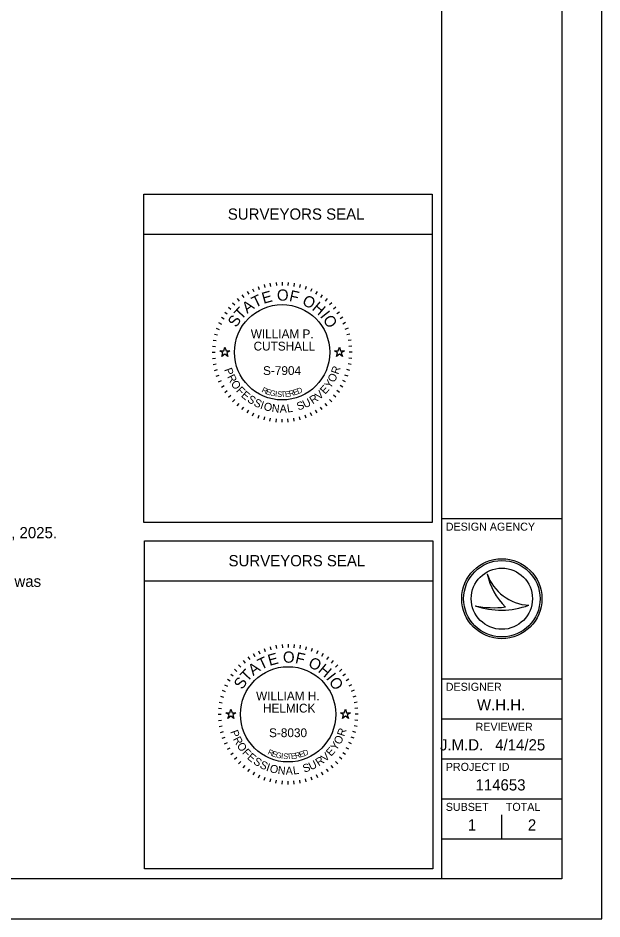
# Model space of a CAD drawing. Extents: x 0 to 34, y 0 to 22.
# Drawn here: x 26.71 to 34, y 0 to 11.25 of the extents above; entities that cross this region are included whole.
import ezdxf

# ---------------------------------------------------------------- set-up
doc = ezdxf.new("R2010")
doc.units = 0
for name, color, linetype in [('SH_Border', 7, 'Continuous'), ('SH_Cut_Line', 7, 'Continuous'), ('SH_Data', 7, 'Continuous'), ('SH_Seal', 7, 'Continuous'), ('SH_Text', 7, 'Continuous')]:
    doc.layers.add(name, color=color, linetype=linetype)

msp = doc.modelspace()

# ---------------------------------------------------------------- linework, layer by layer
at = {"layer": 'SH_Border'}
for p, q in [((32, 0.5), (32, 21.5)), ((32, 5), (33.5, 5)), ((32, 3), (33.5, 3)), ((32, 2.5), (33.5, 2.5)), ((32, 2), (33.5, 2)), ((32, 1.5), (33.5, 1.5)), ((32, 1), (33.5, 1))]:
    msp.add_line(p, q, dxfattribs=at)
msp.add_lwpolyline([(1.5, 21.5), (33.5, 21.5), (33.5, 0.5), (1.5, 0.5)], close=True, dxfattribs=at)
at = {"layer": 'SH_Cut_Line'}
msp.add_lwpolyline([(0, 0), (34, 0), (34, 22), (0, 22)], close=True, dxfattribs=at)
at = {"layer": 'SH_Data'}
for p, q in [((28.279, 8.554), (31.879, 8.554)), ((32.567, 4.31), (32.567, 4.31)), ((28.288, 4.225), (31.888, 4.225)), ((32.75, 4), (32.75, 4)), ((32.417, 3.91), (32.417, 3.91)), ((33.087, 3.919), (33.087, 3.919)), ((32.75, 1), (32.75, 1.3))]:
    msp.add_line(p, q, dxfattribs=at)
for points in [[(28.279, 9.054), (31.879, 9.054), (31.879, 4.954), (28.279, 4.954)], [(28.288, 4.725), (31.888, 4.725), (31.888, 0.625), (28.288, 0.625)]]:
    msp.add_lwpolyline(points, close=True, dxfattribs=at)
for radius in [0.5, 0.477, 0.477, 0.382]:
    msp.add_circle((32.75, 4), radius, dxfattribs=at)
for centre, radius, start, end in [((33.116, 4.498), 0.58, 198.9257, 198.9319), ((33.347, 4.47), 0.796, 191.6379, 191.6421), ((33.116, 4.498), 0.58, 198.9319, 267.1657), ((33.347, 4.47), 0.796, 191.6421, 226.0947), ((32.739, 4.87), 1.013, 251.4576, 290.0832), ((32.648, 5.154), 1.266, 259.4964, 259.4995), ((32.739, 4.87), 1.013, 251.4527, 251.4576), ((32.648, 5.154), 1.266, 259.4995, 276.6672)]:
    msp.add_arc(centre, radius, start, end, dxfattribs=at)
at = {"layer": 'SH_Seal'}
for p, q in [((29.708, 7.901), (29.722, 7.863)), ((29.781, 7.924), (29.791, 7.885)), ((29.855, 7.94), (29.862, 7.901)), ((29.931, 7.95), (29.935, 7.91)), ((30.007, 7.953), (30.007, 7.913)), ((30.084, 7.95), (30.08, 7.91)), ((30.159, 7.94), (30.152, 7.901)), ((30.234, 7.924), (30.224, 7.885)), ((30.307, 7.901), (30.293, 7.863)), ((29.506, 7.795), (29.528, 7.762)), ((29.57, 7.836), (29.59, 7.802)), ((29.638, 7.871), (29.655, 7.835)), ((30.377, 7.871), (30.36, 7.835)), ((30.445, 7.836), (30.425, 7.802)), ((30.509, 7.795), (30.486, 7.762)), ((29.389, 7.697), (29.417, 7.669)), ((29.445, 7.749), (29.471, 7.718)), ((30.57, 7.749), (30.544, 7.718)), ((30.626, 7.697), (30.598, 7.669)), ((29.291, 7.58), (29.323, 7.557)), ((29.337, 7.641), (29.368, 7.615)), ((30.678, 7.641), (30.647, 7.615)), ((30.724, 7.58), (30.691, 7.557)), ((29.214, 7.448), (29.251, 7.431)), ((29.25, 7.516), (29.284, 7.496)), ((30.765, 7.516), (30.731, 7.496)), ((30.8, 7.448), (30.764, 7.431)), ((29.185, 7.378), (29.223, 7.364)), ((30.83, 7.378), (30.792, 7.364)), ((29.146, 7.23), (29.185, 7.223)), ((29.162, 7.305), (29.201, 7.295)), ((30.853, 7.305), (30.814, 7.295)), ((30.869, 7.23), (30.83, 7.223)), ((29.136, 7.155), (29.176, 7.151)), ((30.879, 7.155), (30.839, 7.151)), ((29.132, 7.078), (29.172, 7.078)), ((29.136, 7.002), (29.176, 7.006)), ((30.879, 7.002), (30.839, 7.006)), ((30.882, 7.078), (30.842, 7.078)), ((29.146, 6.927), (29.185, 6.933)), ((30.869, 6.927), (30.83, 6.933)), ((29.162, 6.852), (29.201, 6.862)), ((29.185, 6.779), (29.223, 6.793)), ((30.83, 6.779), (30.792, 6.793)), ((30.853, 6.852), (30.814, 6.862)), ((29.214, 6.709), (29.251, 6.726)), ((29.25, 6.641), (29.284, 6.661)), ((30.765, 6.641), (30.731, 6.661)), ((30.8, 6.709), (30.764, 6.726)), ((29.291, 6.577), (29.323, 6.6)), ((29.337, 6.516), (29.368, 6.542)), ((30.678, 6.516), (30.647, 6.542)), ((30.724, 6.577), (30.691, 6.6)), ((29.389, 6.46), (29.417, 6.488)), ((29.445, 6.408), (29.471, 6.439)), ((30.57, 6.408), (30.544, 6.439)), ((30.626, 6.46), (30.598, 6.488)), ((29.506, 6.362), (29.528, 6.394)), ((29.57, 6.321), (29.59, 6.355)), ((29.638, 6.285), (29.655, 6.322)), ((30.377, 6.285), (30.36, 6.322)), ((30.445, 6.321), (30.425, 6.355)), ((30.509, 6.362), (30.486, 6.394)), ((29.708, 6.256), (29.722, 6.294)), ((29.781, 6.233), (29.791, 6.272)), ((29.855, 6.217), (29.862, 6.256)), ((29.931, 6.207), (29.935, 6.247)), ((30.007, 6.203), (30.007, 6.243)), ((30.084, 6.207), (30.08, 6.247)), ((30.159, 6.217), (30.152, 6.256)), ((30.234, 6.233), (30.224, 6.272)), ((30.307, 6.256), (30.293, 6.294)), ((29.783, 3.379), (29.797, 3.341)), ((29.856, 3.401), (29.866, 3.363)), ((29.93, 3.418), (29.937, 3.379)), ((30.006, 3.428), (30.01, 3.388)), ((30.082, 3.431), (30.082, 3.391)), ((30.159, 3.428), (30.155, 3.388)), ((30.234, 3.418), (30.227, 3.379)), ((30.309, 3.401), (30.299, 3.363)), ((30.382, 3.379), (30.368, 3.341)), ((29.581, 3.273), (29.603, 3.24)), ((29.645, 3.314), (29.665, 3.279)), ((29.713, 3.349), (29.73, 3.313)), ((30.452, 3.349), (30.435, 3.313)), ((30.52, 3.314), (30.5, 3.279)), ((30.584, 3.273), (30.561, 3.24)), ((29.464, 3.175), (29.492, 3.147)), ((29.52, 3.227), (29.546, 3.196)), ((30.645, 3.227), (30.619, 3.196)), ((30.701, 3.175), (30.673, 3.147)), ((29.366, 3.058), (29.398, 3.035)), ((29.412, 3.119), (29.443, 3.093)), ((30.753, 3.119), (30.722, 3.093)), ((30.799, 3.058), (30.766, 3.035)), ((29.289, 2.926), (29.326, 2.909)), ((29.325, 2.994), (29.359, 2.974)), ((30.84, 2.994), (30.806, 2.974)), ((30.875, 2.926), (30.839, 2.909)), ((29.26, 2.856), (29.298, 2.842)), ((30.905, 2.856), (30.867, 2.842)), ((29.221, 2.708), (29.26, 2.701)), ((29.237, 2.783), (29.276, 2.772)), ((30.928, 2.783), (30.889, 2.772)), ((30.944, 2.708), (30.905, 2.701)), ((29.211, 2.633), (29.251, 2.629)), ((30.954, 2.633), (30.914, 2.629)), ((29.207, 2.556), (29.247, 2.556)), ((29.211, 2.48), (29.251, 2.484)), ((30.954, 2.48), (30.914, 2.484)), ((30.957, 2.556), (30.917, 2.556)), ((29.221, 2.404), (29.26, 2.411)), ((30.944, 2.404), (30.905, 2.411)), ((29.237, 2.33), (29.276, 2.34)), ((29.26, 2.257), (29.298, 2.271)), ((30.905, 2.257), (30.867, 2.271)), ((30.928, 2.33), (30.889, 2.34)), ((29.289, 2.187), (29.326, 2.203)), ((29.325, 2.119), (29.359, 2.139)), ((30.84, 2.119), (30.806, 2.139)), ((30.875, 2.187), (30.839, 2.203)), ((29.366, 2.054), (29.398, 2.077)), ((30.799, 2.054), (30.766, 2.077)), ((29.412, 1.994), (29.443, 2.02)), ((29.464, 1.938), (29.492, 1.966)), ((29.52, 1.886), (29.546, 1.917)), ((30.645, 1.886), (30.619, 1.917)), ((30.701, 1.938), (30.673, 1.966)), ((30.753, 1.994), (30.722, 2.02)), ((29.581, 1.84), (29.603, 1.872)), ((29.645, 1.799), (29.665, 1.833)), ((30.52, 1.799), (30.5, 1.833)), ((30.584, 1.84), (30.561, 1.872)), ((29.713, 1.763), (29.73, 1.8)), ((29.783, 1.734), (29.797, 1.772)), ((29.856, 1.711), (29.866, 1.75)), ((29.93, 1.695), (29.937, 1.734)), ((30.006, 1.685), (30.01, 1.724)), ((30.082, 1.681), (30.082, 1.721)), ((30.159, 1.685), (30.155, 1.724)), ((30.234, 1.695), (30.227, 1.734)), ((30.309, 1.711), (30.299, 1.75)), ((30.382, 1.734), (30.368, 1.772)), ((30.452, 1.763), (30.435, 1.8))]:
    msp.add_line(p, q, dxfattribs=at)
for points in [[(29.231, 7.098), (29.278, 7.098), (29.292, 7.143), (29.307, 7.098), (29.354, 7.098), (29.316, 7.071), (29.33, 7.026), (29.292, 7.054), (29.254, 7.026), (29.269, 7.071)], [(30.661, 7.098), (30.708, 7.098), (30.722, 7.143), (30.737, 7.098), (30.784, 7.098), (30.746, 7.071), (30.76, 7.026), (30.722, 7.054), (30.684, 7.026), (30.699, 7.071)], [(29.306, 2.576), (29.353, 2.576), (29.367, 2.621), (29.382, 2.576), (29.429, 2.576), (29.391, 2.549), (29.405, 2.504), (29.367, 2.532), (29.329, 2.504), (29.344, 2.549)], [(30.736, 2.576), (30.783, 2.576), (30.797, 2.621), (30.812, 2.576), (30.859, 2.576), (30.821, 2.549), (30.835, 2.504), (30.797, 2.532), (30.759, 2.504), (30.774, 2.549)]]:
    msp.add_lwpolyline(points, close=True, dxfattribs=at)
for centre in [(30.007, 7.078), (30.082, 2.556)]:
    msp.add_circle(centre, 0.595, dxfattribs=at)

# ---------------------------------------------------------------- texts
at = {"layer": 'SH_Data'}
for s, height, p in [('SURVEYORS SEAL', 0.14, (29.329, 8.734)), ('DESIGN AGENCY', 0.1, (32.05, 4.85)), ('SURVEYORS SEAL', 0.14, (29.338, 4.405)), ('DESIGNER', 0.1, (32.05, 2.85)), ('W.H.H.', 0.14, (32.439, 2.605)), ('REVIEWER', 0.1, (32.422, 2.35)), ('4/14/25', 0.14, (32.667, 2.105)), ('J.M.D.', 0.14, (31.977, 2.105)), ('PROJECT ID', 0.1, (32.05, 1.85)), ('114653', 0.14, (32.421, 1.605)), ('SUBSET', 0.1, (32.05, 1.35)), ('TOTAL', 0.1, (32.8, 1.35)), ('1', 0.14, (32.325, 1.105)), ('2', 0.14, (33.075, 1.105))]:
    msp.add_text(s, height=height, dxfattribs=at).set_placement(p)
at = {"layer": 'SH_Seal'}
for s, height, rotation, p in [('T', 0.14, 25.7167, (29.669, 7.63)), ('E', 0.14, 15.7571, (29.776, 7.682)), ('O', 0.14, 359.7812, (29.942, 7.723)), ('F', 0.14, 347.4362, (30.088, 7.72)), ('O', 0.14, 332.2586, (30.247, 7.68)), ('A', 0.14, 36.4747, (29.571, 7.557)), ('H', 0.14, 319.9136, (30.371, 7.615)), ('S', 0.14, 57.1924, (29.436, 7.38)), ('T', 0.14, 46.4344, (29.496, 7.475)), ('I', 0.14, 308.367, (30.474, 7.527)), ('O', 0.14, 303.1491, (30.51, 7.487)), ('P', 0.1, 289.7431, (29.283, 6.863)), ('R', 0.1, 70.983, (30.708, 6.795)), ('R', 0.1, 296.9802, (29.317, 6.771)), ('O', 0.1, 62.7428, (30.657, 6.692)), ('O', 0.1, 304.7158, (29.361, 6.686)), ('F', 0.1, 312.956, (29.427, 6.594)), ('R', 0.07, 334.487, (29.745, 6.584)), ('E', 0.1, 48.2687, (30.544, 6.546)), ('Y', 0.1, 55.5058, (30.607, 6.618)), ('E', 0.1, 319.6885, (29.488, 6.529)), ('S', 0.1, 326.9255, (29.563, 6.467)), ('E', 0.07, 341.04, (29.798, 6.559)), ('G', 0.07, 347.4752, (29.849, 6.54)), ('I', 0.07, 353.7858, (29.916, 6.525)), ('S', 0.07, 356.8926, (29.943, 6.521)), ('T', 0.07, 3.0061, (29.993, 6.517)), ('E', 0.07, 6.0117, (30.046, 6.52)), ('R', 0.07, 11.9184, (30.1, 6.526)), ('E', 0.07, 17.6836, (30.157, 6.539)), ('D', 0.07, 23.3052, (30.208, 6.555)), ('R', 0.1, 33.296, (30.389, 6.426)), ('V', 0.1, 41.0316, (30.469, 6.479)), ('S', 0.1, 334.1626, (29.643, 6.416)), ('I', 0.1, 341.3997, (29.726, 6.376)), ('O', 0.1, 345.1351, (29.769, 6.361)), ('N', 0.1, 353.3752, (29.873, 6.334)), ('A', 0.1, 1.1108, (29.977, 6.323)), ('L', 0.1, 8.3479, (30.074, 6.325)), ('S', 0.1, 18.3234, (30.208, 6.35)), ('U', 0.1, 25.5604, (30.291, 6.377)), ('T', 0.14, 25.7167, (29.744, 3.108)), ('E', 0.14, 15.7571, (29.851, 3.16)), ('O', 0.14, 359.7812, (30.017, 3.201)), ('F', 0.14, 347.4362, (30.163, 3.198)), ('O', 0.14, 332.2586, (30.322, 3.158)), ('A', 0.14, 36.4747, (29.646, 3.034)), ('H', 0.14, 319.9136, (30.446, 3.092)), ('T', 0.14, 46.4344, (29.571, 2.953)), ('I', 0.14, 308.367, (30.549, 3.005)), ('S', 0.14, 57.1924, (29.511, 2.858)), ('O', 0.14, 303.1491, (30.585, 2.965)), ('P', 0.1, 289.7431, (29.358, 2.34)), ('R', 0.1, 70.983, (30.783, 2.273)), ('R', 0.1, 296.9802, (29.392, 2.249)), ('O', 0.1, 62.7428, (30.733, 2.17)), ('O', 0.1, 304.7158, (29.436, 2.164)), ('E', 0.1, 48.2687, (30.619, 2.024)), ('Y', 0.1, 55.5058, (30.682, 2.096)), ('F', 0.1, 312.956, (29.502, 2.072)), ('E', 0.1, 319.6885, (29.563, 2.007)), ('R', 0.07, 334.487, (29.82, 2.061)), ('E', 0.07, 341.04, (29.873, 2.036)), ('G', 0.07, 347.4752, (29.924, 2.018)), ('I', 0.07, 353.7858, (29.991, 2.003)), ('S', 0.07, 356.8926, (30.018, 1.999)), ('T', 0.07, 3.0061, (30.068, 1.995)), ('E', 0.07, 6.0117, (30.121, 1.998)), ('R', 0.07, 11.9184, (30.175, 2.004)), ('E', 0.07, 17.6836, (30.232, 2.016)), ('D', 0.07, 23.3052, (30.283, 2.033)), ('V', 0.1, 41.0316, (30.544, 1.957)), ('S', 0.1, 326.9255, (29.638, 1.945)), ('S', 0.1, 334.1626, (29.718, 1.894)), ('I', 0.1, 341.3997, (29.801, 1.854)), ('O', 0.1, 345.1351, (29.844, 1.838)), ('S', 0.1, 18.3234, (30.283, 1.827)), ('U', 0.1, 25.5604, (30.366, 1.855)), ('R', 0.1, 33.296, (30.464, 1.904)), ('N', 0.1, 353.3752, (29.948, 1.812)), ('A', 0.1, 1.1108, (30.052, 1.801)), ('L', 0.1, 8.3479, (30.149, 1.803))]:
    msp.add_text(s, height=height, rotation=rotation, dxfattribs=at).set_placement(p)
for s, p in [('WILLIAM P.', (29.616, 7.253)), ('CUTSHALL', (29.651, 7.1)), ('S-7904', (29.769, 6.794)), ('WILLIAM H.', (29.682, 2.731)), ('HELMICK', (29.768, 2.578)), ('S-8030', (29.844, 2.271))]:
    msp.add_text(s, height=0.11, dxfattribs=at).set_placement(p)
at = {"layer": 'SH_Text'}
for s, p in [('I, William Cutshall, P.S. have conducted a survey of the existing conditions for the Ohio Department of Transportation between 12, 2024 and 02, 2025.  ', (14.751, 4.755)), (' line of Right of Way and the existing Right of Way limits as necessary for the property takes contained herein.   All of my work contained herein was ', (14.751, 4.148))]:
    msp.add_text(s, height=0.14, dxfattribs=at).set_placement(p)

doc.saveas('drawing.dxf')
